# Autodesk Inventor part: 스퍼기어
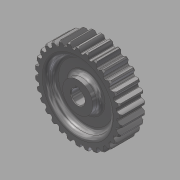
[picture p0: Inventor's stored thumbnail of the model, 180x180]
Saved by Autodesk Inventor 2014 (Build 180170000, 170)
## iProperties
Created: 2015-11
Part Number: 스퍼기어
Material: 강철, 탄소
Document SubType Name: Modeling
Designer: mduedu
Density: 7.87 g/cm^3
Mass: 274.745 g
Surface Area: 132.169 cm^2
Volume: 34.9104 cm^3
Appearance: 반광택
Author: mduedu
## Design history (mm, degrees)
sketch "스케치1"
  geometry: C1 r 28.75 at (0, 0); 1 further point
  constraints: 1 centre point, 1 coincident
  dimensions: "d0" = 57.5 diameter of C1
extrude "돌출1" new body sketch "스케치1" stored distance "d2" = 18; taper "d3" = 0 deg
sketch "스케치2" dims "d4" = 60
  geometry: L1 (0, 0)-(0, 32); L2 (-32, 0)-(32, 0); L3 (-2.07, 0)-(-2.07, 40.614); L4 (-2.07, 40.614)-(-1.57, 40.614); L5 (-1.57, 40.614)-(-1.57, 0); L6 (-0.57, 0)-(-0.57, 40.614); L7 (-0.57, 40.614)-(0, 40.614); L8 (0, 40.614)-(0, 0); A1 r 32 centre (0, 0) between (0.57, 31.995) and (-0.57, 31.995); A2 r 21.436 centre (18.143, 21.54) between (-0.57, 31.995) and (-2.07, 28.675); A3 r 21.436 centre (-18.143, 21.54) between (2.07, 28.675) and (0.57, 31.995); A4 r 32 centre (0, 0) between (32, 0) and (0.57, 31.995); A5 r 32 centre (0, 0) between (-0.57, 31.995) and (32, 0); A6 r 28.75 centre (0, 0) between (2.07, 28.675) and (-2.07, 28.675); 4 further points
  constraints: 17 point on circle, 16 end point, 6 centre point, 6 point on line, 5 perpendicular, 4 coincident, 3 symmetric about line, 2 collinear, 1 midpoint, 1 parallel, 1 vertical, 6 other
  dimensions: "d6" = 64 diameter of A1; "d7" = 0.5 distance between parallel lines of L5 L3; "d8" = 1 distance between parallel lines of L6 L5; "d9" = 40.61409 distance of L4.end L5.end; "d10" = 1.57 distance between parallel lines of L8 L5
extrude "돌출2" join sketch "스케치2" stored distance "d11" = 18; taper "d12" = 0 deg
fillet "모깎기1" dims "d16" = 0.5
chamfer "모따기3" distance "d26" = 1; stored, may be unused: second distance "d27" = 2, angle "d28" = 45 deg
sketch "스케치3"
  geometry: C1 r 23 at (0, 0); C2 r 11 at (0, 0); 1 further point
  constraints: 2 centre point, 2 coincident
  dimensions: "d32" = 46 diameter of C1; "d33" = 22 diameter of C2
extrude "돌출3" cut sketch "스케치3" distance "d34" = 6; taper "d35" = 0 deg
fillet "모깎기2" dims "d36" = 3
hole "구멍1" diameter "d39" = 10; stored, may be unused: countersink angle "d43" = 90 deg, drill point angle "d45" = 118 deg; dims "d37" = 10, "d38" = 10, "d40" = 6, "d41" = 4, "d42" = 2, "d44" = 8
sketch "스케치5"
  geometry: L1 (-1.5, 0)-(1.5, 0); L2 (1.5, 0)-(1.5, 6.4); L3 (1.5, 6.4)-(-1.5, 6.4); L4 (-1.5, 6.4)-(-1.5, 0); 2 further points
  constraints: 8 end point, 2 parallel, 1 coincident, 1 horizontal, 1 midpoint, 1 perpendicular
  dimensions: "d46" = 3 distance of L2.end L3.end; "d48" = 6.4 distance of L1.end L2.end
extrude "돌출4" cut sketch "스케치5" stored distance "d49" = 6; taper "d50" = 0 deg
chamfer "모따기4" distance "d51" = 0.5; stored, may be unused: second distance "d52" = 2, angle "d53" = 45 deg
node "솔리드1"
pattern_circular "원형 패턴3" dims "d30" = 360 deg
mirror "대칭1"
